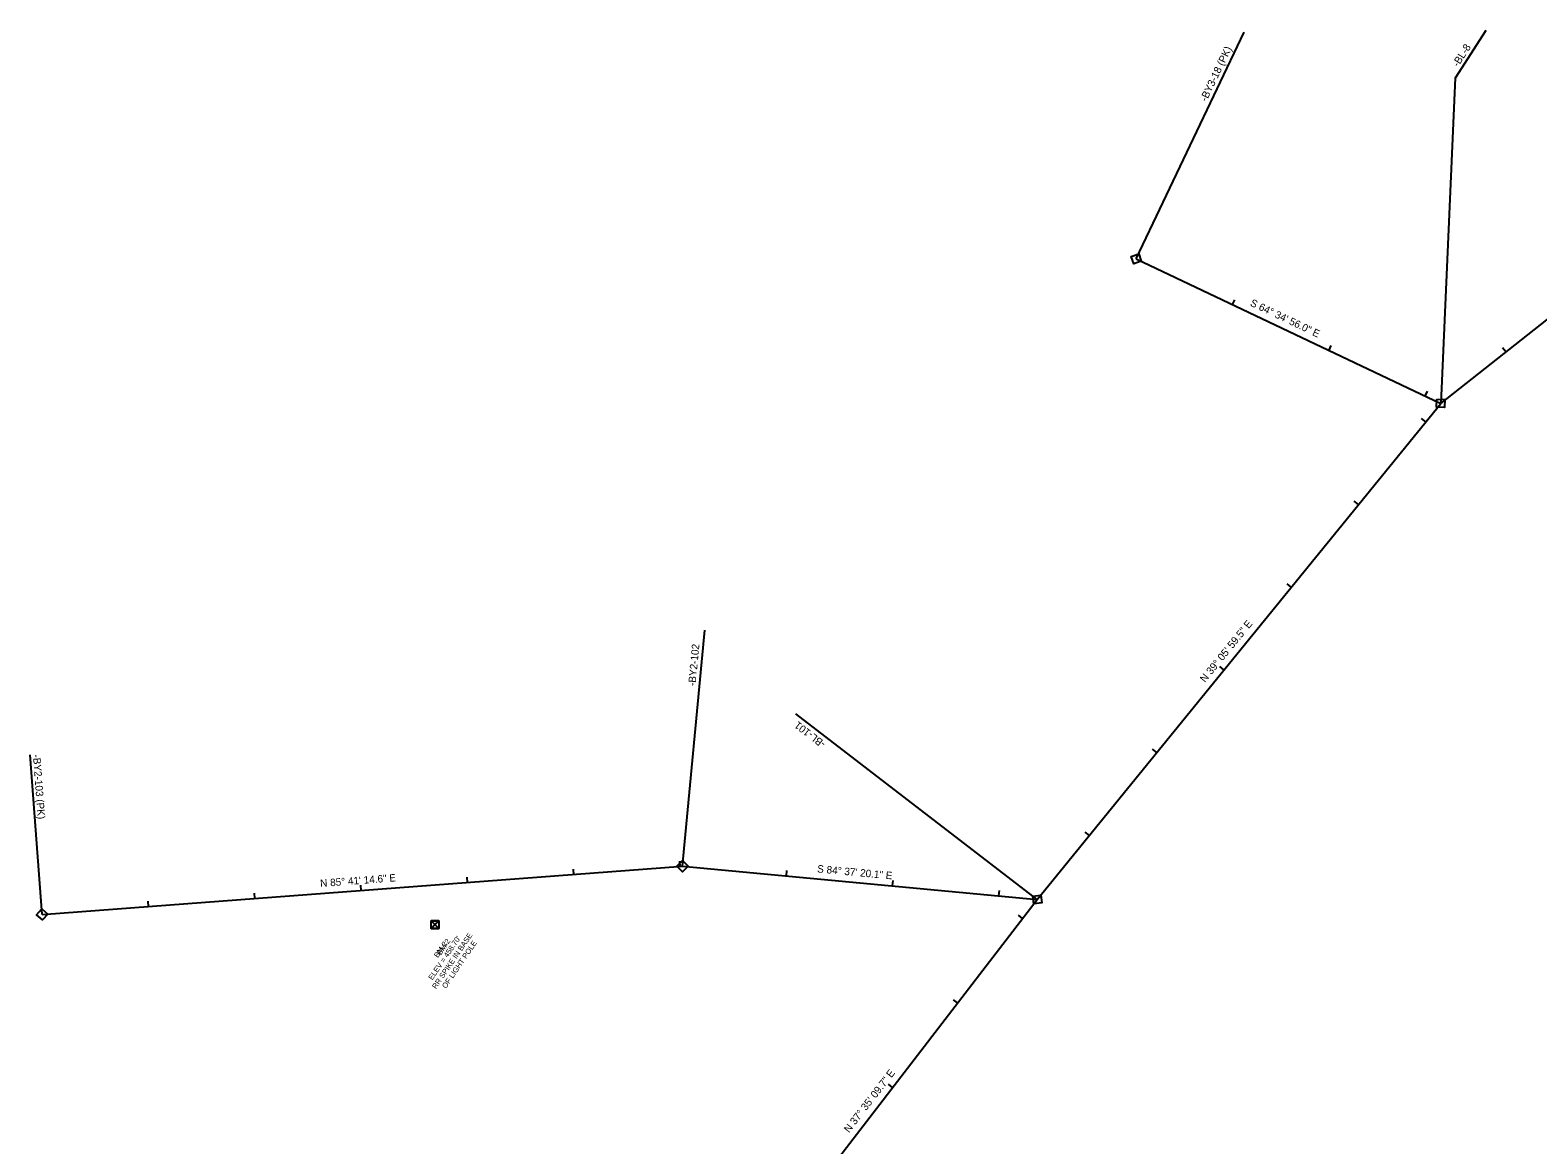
# Model space of a CAD drawing. Extents: x 1975258 to 1978652, y 778250 to 783549.
# Drawn here: x 1975497 to 1976910, y 779305 to 780351 of the extents above; entities that cross this region are included whole.
import ezdxf

# ---------------------------------------------------------------- set-up
doc = ezdxf.new("R2010")
doc.units = 0
for name, color, linetype in [('Prop Drainage Structure Drop Inlet Grate 2 Narrow Slots and Flat Grates 840 29 Label', 7, 'Continuous'), ('Prop Drainage Structure Drop Inlet Grate 2 Narrow Slots and Sag Grates 840 24 CELL', 7, 'Continuous'), ('Prop Erosion Rip Rap Pad at Outlet CELL', 7, 'Continuous'), ('Prop SS Fill Line', 7, 'Continuous'), ('Prop SS Transition Line', 7, 'Continuous'), ('Sheet Data Field CELL', 7, 'Continuous'), ('Sheet Sticker Preliminary CELL', 7, 'Continuous'), ('Sheet Typical CELL', 7, 'Continuous')]:
    doc.layers.add(name, color=color, linetype=linetype)

msp = doc.modelspace()

# ---------------------------------------------------------------- linework, layer by layer
at = {"layer": 'Prop Drainage Structure Drop Inlet Grate 2 Narrow Slots and Sag Grates 840 24 CELL'}
for p, q in [((1976533.9, 780136.3), (1976634.9, 780348.8)), ((1976833.2, 780306.1), (1976861.9, 780350.8)), ((1976819.9, 780000.5), (1976833.2, 780306.1)), ((1976108.4, 779566.6), (1976129.3, 779788)), ((1976441, 779535.3), (1976214.7, 779709.5)), ((1975508, 779521.3), (1975496.7, 779670.9))]:
    msp.add_line(p, q, dxfattribs=at)
at = {"layer": 'Prop SS Transition Line'}
for p, q in [((1976533.9, 780136.3), (1976533.9, 780136.3)), ((1976819.3, 780000.7), (1976819.3, 780000.7)), ((1976108.4, 779566.6), (1976108.4, 779566.6)), ((1976441, 779535.3), (1976441, 779535.3)), ((1975508, 779521.3), (1975508, 779521.3))]:
    msp.add_line(p, q, dxfattribs=at)
for points in [[(1976536.2, 780141), (1976538.6, 780134), (1976531.6, 780131.6), (1976529.2, 780138.6)], [(1976815.6, 780004.5), (1976823.1, 780004.4), (1976822.9, 779996.9), (1976815.5, 779997.1)], [(1976103.2, 779566.6), (1976108.5, 779571.9), (1976113.7, 779566.6), (1976108.5, 779561.4)], [(1976436.9, 779538.5), (1976444.3, 779539.4), (1976445.2, 779532.1), (1976437.8, 779531.1)], [(1975507.6, 779526.5), (1975513.3, 779521.7), (1975508.4, 779516.1), (1975502.8, 779520.9)]]:
    msp.add_lwpolyline(points, close=True, dxfattribs=at)
at = {"layer": 'Sheet Data Field CELL'}
for p, q in [((1976533.9, 780136.3), (1976536.1, 780140.8)), ((1976624.2, 780093.4), (1976626.4, 780097.9)), ((1976714.6, 780050.5), (1976716.7, 780055)), ((1976880.3, 780048.9), (1976877.2, 780052.9)), ((1976804.9, 780007.6), (1976807, 780012.1)), ((1976805.3, 779983.5), (1976801.4, 779986.6)), ((1976742.2, 779905.9), (1976738.3, 779909)), ((1976679.1, 779828.3), (1976675.2, 779831.4)), ((1976616.1, 779750.7), (1976612.2, 779753.8)), ((1976553, 779673.1), (1976549.1, 779676.2)), ((1976489.9, 779595.5), (1976486, 779598.6)), ((1976106.3, 779566.4), (1976105.9, 779571.4)), ((1975906.9, 779551.4), (1975906.5, 779556.4)), ((1976006.6, 779558.9), (1976006.2, 779563.9)), ((1976205.9, 779557.4), (1976206.3, 779562.4)), ((1975807.2, 779543.9), (1975806.8, 779548.9)), ((1976305.4, 779548.1), (1976305.9, 779553)), ((1976405, 779538.7), (1976405.5, 779543.7)), ((1975607.7, 779528.8), (1975607.3, 779533.8)), ((1975707.4, 779536.4), (1975707.1, 779541.3)), ((1975508, 779521.3), (1975507.6, 779526.3)), ((1976427.3, 779517.5), (1976423.4, 779520.5)), ((1976366.3, 779438.3), (1976362.4, 779441.3)), ((1976305.3, 779359), (1976301.4, 779362.1))]:
    msp.add_line(p, q, dxfattribs=at)
at = {"layer": 'Sheet Sticker Preliminary CELL'}
msp.add_line((1975876.2, 779511.8), (1975876.2, 779511.8), dxfattribs=at)
msp.add_lwpolyline([(1975872.6, 779515.4), (1975879.8, 779515.4), (1975879.8, 779508.2), (1975872.6, 779508.2)], close=True, dxfattribs=at)
for points in [[(1975879.8, 779515.4), (1975872.6, 779508.2), (1975876.2, 779511.8), (1975879.8, 779508.2), (1975872.6, 779515.4)], [(1975876.2, 779511.8), (1975879.8, 779515.4), (1975872.6, 779515.4), (1975876.2, 779511.8)], [(1975876.2, 779511.8), (1975872.6, 779508.2), (1975879.8, 779508.2), (1975876.2, 779511.8)]]:
    msp.add_lwpolyline(points, dxfattribs=at)
at = {"layer": 'Sheet Typical CELL'}
for p, q in [((1976819.3, 780000.7), (1977137.6, 780252.1)), ((1976533.9, 780136.3), (1976819.3, 780000.7)), ((1976441, 779535.3), (1976819.3, 780000.7)), ((1975508, 779521.3), (1976108.4, 779566.6)), ((1976108.4, 779566.6), (1976441, 779535.3)), ((1976150.3, 779157.6), (1976441, 779535.3))]:
    msp.add_line(p, q, dxfattribs=at)

# ---------------------------------------------------------------- texts
at = {"layer": 'Prop Drainage Structure Drop Inlet Grate 2 Narrow Slots and Flat Grates 840 29 Label'}
for s, rotation, p in [('S 64%%d 34\' 56.0" E', 334.5822, (1976640, 780092.6)), ('N 39%%d 05\' 59.5" E', 50.9001, (1976598.3, 779738.4)), ('N 85%%d 41\' 14.6" E', 4.3126, (1975768.9, 779547)), ('S 84%%d 37\' 20.1" E', 354.6222, (1976234.4, 779560.8)), ('N 37%%d 35\' 09.7" E', 52.414, (1976264.6, 779316))]:
    msp.add_text(s, height=7, rotation=rotation, dxfattribs=at).set_placement(p)
at = {"layer": 'Prop Drainage Structure Drop Inlet Grate 2 Narrow Slots and Sag Grates 840 24 CELL'}
for s, rotation, p in [('-BY3-18 (PK)', 64.5819, (1976599.7, 780283.3)), ('-BL-8 ', 57.255, (1976835.6, 780315.7)), ('-BY2-102', 84.6246, (1976120.6, 779735.3)), ('-BL-101', 142.4146, (1976243.2, 779682.5)), ('-BY2-103 (PK)', 274.3126, (1975499.3, 779671.1))]:
    msp.add_text(s, height=7, rotation=rotation, dxfattribs=at).set_placement(p)
at = {"layer": 'Prop Erosion Rip Rap Pad at Outlet CELL'}
msp.add_text('BM-2', height=5, rotation=55.8441, dxfattribs=at).set_placement((1975881.8, 779482.7))
at = {"layer": 'Prop SS Fill Line'}
for s, p in [("ELEV = 458.70'", (1975873.8, 779459.3)), ('RR SPIKE IN BASE', (1975877.3, 779451)), ('BM-2', (1975879, 779480.2)), ('OF LIGHT POLE', (1975886.6, 779451.4))]:
    msp.add_text(s, height=5, rotation=55.8441, dxfattribs=at).set_placement(p)

doc.saveas('drawing.dxf')
